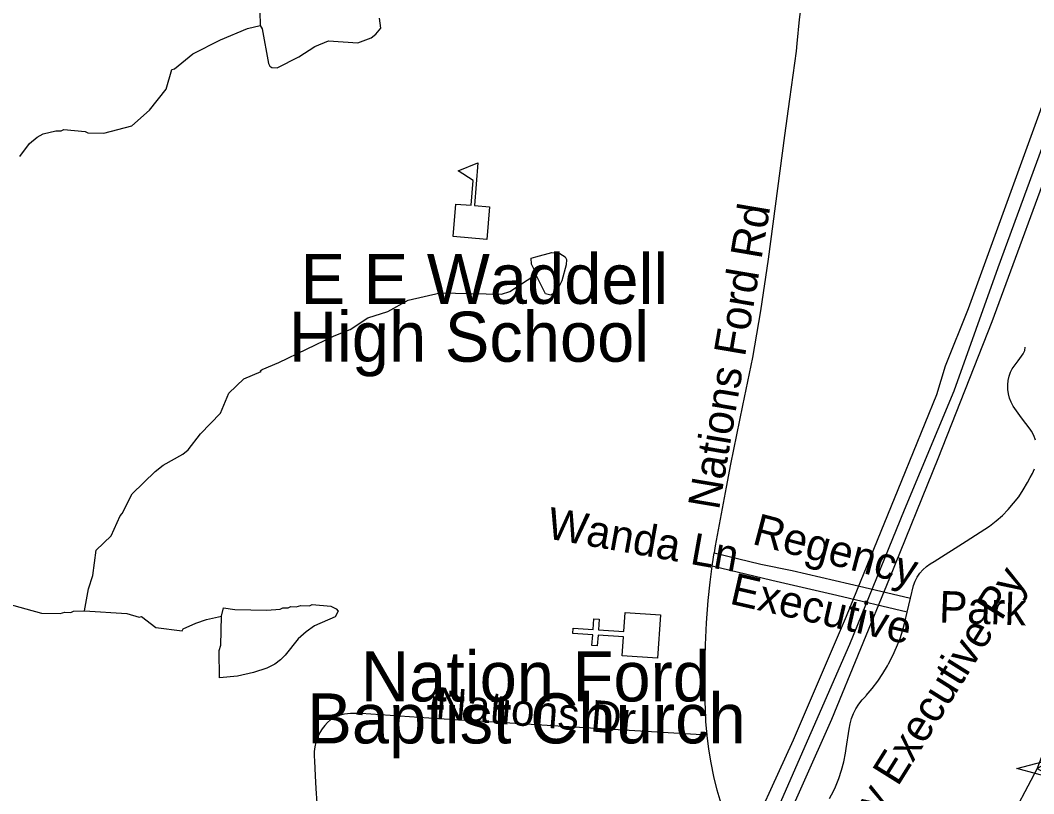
# Model space of a CAD drawing. Extents: x 1383679 to 1536984, y 460658 to 651027.
# Drawn here: x 1430703 to 1433744, y 515092 to 517411 of the extents above; entities that cross this region are included whole.
import ezdxf

# ---------------------------------------------------------------- set-up
doc = ezdxf.new("R2010")
doc.units = 0
for name, color, linetype in [('Exist Cultural Church CELL', 7, 'Continuous'), ('Exist Cultural Church Label', 7, 'Continuous'), ('Exist Cultural Educational Facility Elementary CELL', 7, 'Continuous'), ('Exist Cultural Educational Facility High Label', 7, 'Continuous'), ('Exist Hydrographic Misc Water Feature', 7, 'Continuous'), ('Exist Road Non-System Type 51', 7, 'Continuous'), ('Exist Road Non-System Type 51 Label', 7, 'Continuous'), ('Exist Road Primary Interstate Divided Center Attributed', 7, 'Continuous'), ('Exist Road Primary Interstate Structure Ovrhead Sign Attributed CELL', 7, 'Continuous'), ('Exist Utilities Electrical Transmission Line', 7, 'Continuous')]:
    doc.layers.add(name, color=color, linetype=linetype)

msp = doc.modelspace()

# ---------------------------------------------------------------- linework, layer by layer
at = {"layer": 'Exist Cultural Church CELL'}
msp.add_lwpolyline([(1432508.9, 515505.2), (1432512.6, 515562), (1432436.6, 515567.1), (1432434.5, 515535.1), (1432418.5, 515536.2), (1432420.7, 515568.1), (1432360.7, 515572.1), (1432361.7, 515588.1), (1432421.7, 515584.1), (1432423.9, 515616.1), (1432439.8, 515615), (1432437.7, 515583.1), (1432513.7, 515578), (1432517.6, 515635.5), (1432623.8, 515628.4), (1432615.1, 515498.1)], close=True, dxfattribs=at)
at = {"layer": 'Exist Cultural Educational Facility Elementary CELL'}
msp.add_lwpolyline([(1432001.9, 516762.6), (1432010, 516860.2), (1432055.9, 516856.4), (1432062.2, 516931.2), (1432017.3, 516959.3), (1432076.2, 516983.7), (1432065.5, 516855.6), (1432111.4, 516851.8), (1432103.2, 516754.2)], close=True, dxfattribs=at)
at = {"layer": 'Exist Hydrographic Misc Water Feature'}
for points in [[(1431421.6, 517438), (1431422.8, 517395.5)], [(1431422.8, 517395.5), (1431428.5, 517385.8), (1431448.2, 517281.4), (1431452, 517273.4), (1431457.9, 517269.2), (1431473.9, 517268.8), (1431538.6, 517301.4), (1431587.3, 517332.3), (1431627.7, 517349.3), (1431715.6, 517343.4), (1431756, 517358.5), (1431770.2, 517370.1), (1431784.6, 517387.8), (1431781.2, 517417.9)], [(1430702, 517002.3), (1430730.8, 517041.6), (1430753.3, 517061.1), (1430771.5, 517070.7), (1430809.7, 517079.8), (1430825.7, 517079.5), (1430833.8, 517083.3), (1430897.7, 517077.9), (1430905.6, 517073.7), (1430953.6, 517072.6), (1431038.1, 517094.7), (1431091.1, 517141.5), (1431140.5, 517204.4), (1431157.7, 517264), (1431165.8, 517265.8), (1431220.8, 517310.5), (1431303.7, 517352.6), (1431384.5, 517386.8), (1431422.8, 517395.5)], [(1432249.9, 516649.1), (1432248.8, 516655.7), (1432237.3, 516679.9), (1432235.9, 516697.5), (1432249.8, 516701.7), (1432298.1, 516714.5), (1432322, 516712), (1432337.8, 516701.7), (1432341.7, 516693.6), (1432341.3, 516677.6), (1432328.3, 516629.9), (1432311.6, 516598.3), (1432305.4, 516592.4), (1432295.4, 516586.7), (1432279.4, 516591), (1432249.9, 516649.1)], [(1430896.1, 515639.6), (1430908, 515706.2), (1430920.8, 515746), (1430930.4, 515821.7), (1430975.4, 515864.6), (1431003, 515925.4), (1431008.9, 515931.9), (1431038.2, 515991.2), (1431107.6, 516057.6), (1431132, 516077.1), (1431190.7, 516109.7), (1431207, 516123.4), (1431244.1, 516170.5), (1431303.4, 516233.1), (1431328.7, 516292.5), (1431373.7, 516335.5), (1431426.1, 516358.3), (1431422.3, 516360.4), (1431428.3, 516364.3), (1431478.7, 516385.1), (1431644.5, 516465.3), (1431693, 516484.3), (1431745.7, 516519.1), (1431806.2, 516537.7), (1431866.9, 516572.3), (1431963.4, 516594.1), (1432147.4, 516590), (1432171.5, 516597.5), (1432249.9, 516649.1)], [(1429860.1, 516317.6), (1429905.7, 516256.6), (1430028.4, 516105.8), (1430075.6, 516064.8), (1430122.9, 516037.8), (1430189.8, 515984.3), (1430276.9, 515940.4), (1430308.4, 515917.7), (1430347.6, 515880.8), (1430394.8, 515843.7), (1430457.6, 515784.4), (1430504.5, 515751.6), (1430552, 515710.2), (1430599.6, 515693.2), (1430601.4, 515687.2), (1430654.9, 515664), (1430766.3, 515633.5), (1430822.4, 515632.2), (1430836.4, 515635.9), (1430854.4, 515635.5), (1430862.5, 515639.3), (1430896.1, 515639.6)], [(1430896.1, 515639.6), (1431022.4, 515631.7), (1431060.1, 515621.5), (1431066.2, 515622.7), (1431109.4, 515589.8), (1431189.1, 515580), (1431191.4, 515585.9), (1431229.8, 515603.1), (1431262, 515614.3), (1431306.3, 515624.4)], [(1431306.3, 515624.4), (1431313, 515649.4), (1431346.7, 515644.4), (1431442.7, 515642.3), (1431482.7, 515645.3), (1431490.8, 515649.2), (1431506.8, 515648.8), (1431514.9, 515652.6), (1431530.9, 515652.3), (1431545, 515656), (1431571, 515655.4), (1431579.1, 515659.2), (1431635, 515654), (1431650.8, 515645.6), (1431656.6, 515639.5), (1431648.3, 515621.7), (1431585.7, 515595.1), (1431561.3, 515577.6), (1431536.9, 515556.2), (1431497.7, 515507.1), (1431483.5, 515493.4), (1431467.2, 515479.8), (1431442.9, 515468.3), (1431402.6, 515455.3), (1431354.4, 515444.3), (1431300.3, 515438.8), (1431300, 515521.5), (1431304.3, 515537.4), (1431306.3, 515624.4)]]:
    msp.add_lwpolyline(points, dxfattribs=at)
at = {"layer": 'Exist Road Non-System Type 51'}
msp.add_line((1433364.4, 515635.9), (1433374.2, 515678.2), dxfattribs=at)
for points in [[(1433055.7, 517525.4), (1433040.3, 517413.7), (1433033.3, 517341.9), (1433030.7, 517319.1), (1433011.1, 517174.8), (1432996.5, 517066), (1432946.7, 516694.7), (1432924.1, 516539.9), (1432900, 516400), (1432870.5, 516255.6), (1432834.4, 516080.2), (1432821, 516011.1), (1432788.2, 515835.4), (1432784.8, 515813.6)], [(1433748.9, 516152), (1433743.9, 516165.7), (1433737.5, 516178.8), (1433733.7, 516185.2), (1433707, 516219), (1433682.8, 516254.4), (1433676.5, 516266.1), (1433671.6, 516278.4), (1433668.2, 516291.2), (1433666.4, 516304.3), (1433666.1, 516317.5), (1433667.4, 516330.7), (1433670.3, 516343.6), (1433674.7, 516356.1), (1433679.4, 516366), (1433696.9, 516390.4), (1433712.8, 516410.5), (1433717, 516421.3), (1433718.7, 516431.1)], [(1433374.2, 515678.2), (1433382.8, 515715.9), (1433387.9, 515728.9), (1433394.5, 515741.3), (1433402.3, 515752.9), (1433411.5, 515763.5), (1433421.8, 515773), (1433433, 515781.3), (1433445.2, 515788.3), (1433541.5, 515849.3), (1433611.8, 515894.3), (1433631.4, 515909.6), (1433650, 515926.2), (1433667.5, 515943.9), (1433683.8, 515962.6), (1433699, 515982.4), (1433712.8, 516003), (1433725.3, 516024.6), (1433733.1, 516039.7), (1433740.3, 516052.4), (1433746.1, 516065.8)], [(1432778.8, 515773.9), (1432779.7, 515780.6), (1432784.8, 515813.6)], [(1432784.8, 515813.6), (1432924.8, 515780.2), (1433018.7, 515761.5), (1433234, 515711), (1433374.2, 515678.2)], [(1432764.1, 515267.1), (1432760.5, 515308.3), (1432758.9, 515338.7), (1432757.4, 515405.1), (1432757.5, 515471.5), (1432759.1, 515538), (1432762.4, 515604.3), (1432767.2, 515670.6), (1432772.7, 515725.7), (1432778.8, 515773.9)], [(1433364.4, 515635.9), (1433153.4, 515686), (1432957.9, 515731), (1432778.8, 515773.9)], [(1433130.9, 515077.6), (1433142.8, 515099.5), (1433149, 515112.4), (1433158.8, 515136.9), (1433167, 515161.9), (1433173.8, 515187.4), (1433179, 515213.2), (1433181.2, 515227.4), (1433190.2, 515285.5), (1433193, 515301.5), (1433197.3, 515317), (1433203.2, 515332.1), (1433210.4, 515346.5), (1433219.1, 515360.1), (1433229, 515372.9), (1433240.1, 515384.6), (1433241.4, 515385.8), (1433259.2, 515406.9), (1433275.8, 515428.9), (1433291.1, 515451.9), (1433305, 515475.6), (1433308.1, 515481.5), (1433321.1, 515506), (1433332.7, 515531.2), (1433342.8, 515557), (1433351.4, 515583.3), (1433357.6, 515606), (1433364.4, 515635.9)], [(1432764.1, 515267.1), (1432396.7, 515289.4), (1432075, 515309.3), (1431957.8, 515316.6), (1431725.9, 515331.7), (1431711.6, 515332.4), (1431693.4, 515332), (1431675.4, 515330), (1431663.4, 515327.6), (1431656.3, 515325.4), (1431648.7, 515322.5), (1431644.6, 515320), (1431634.1, 515313.2), (1431624.5, 515305.2), (1431616.5, 515295.9), (1431608.5, 515286.1), (1431602.1, 515274.9), (1431600.9, 515272.6), (1431594.7, 515259.7), (1431590, 515246.4), (1431586.7, 515232.6), (1431584.9, 515218.6), (1431584.6, 515204.5), (1431585.8, 515189.9), (1431588.2, 515145.3), (1431590.3, 515107.6), (1431598.9, 514975.7)], [(1432853.3, 514917.4), (1432837.1, 514968.6), (1432805.9, 515061.9), (1432794.5, 515102.2), (1432784.6, 515142.8), (1432776.2, 515183.8), (1432769.4, 515225.1), (1432764.2, 515266.6), (1432764.1, 515267.1)]]:
    msp.add_lwpolyline(points, dxfattribs=at)
at = {"layer": 'Exist Road Primary Interstate Divided Center Attributed'}
msp.add_lwpolyline([(1434792.2, 518497.9), (1434771.6, 518430.6), (1434687.2, 518142.5), (1434645.4, 517998.2), (1434587, 517820.2), (1434521.5, 517611.2), (1434427.2, 517293.6), (1434330.2, 516967.1), (1434222.5, 516626.2), (1434131.1, 516331.3), (1434065.6, 516116.8), (1434007.1, 515926.4), (1433922.1, 515639.8), (1433859.8, 515448), (1433839.9, 515390.2), (1433803.8, 515299.5), (1433754.3, 515167.2), (1433661.4, 514990.9)], dxfattribs=at)
at = {"layer": 'Exist Road Primary Interstate Structure Ovrhead Sign Attributed CELL'}
msp.add_lwpolyline([(1433811.1, 515135.6), (1433693.4, 515167.2), (1433811.1, 515198.7), (1433754.3, 515167.2)], close=True, dxfattribs=at)
at = {"layer": 'Exist Utilities Electrical Transmission Line'}
for points in [[(1432134, 512767.1), (1432381.7, 513046.2), (1432422.5, 513091.6), (1432431.9, 513165.3), (1432418.2, 513377.9), (1432408.5, 513600), (1432405.7, 513658), (1432437.3, 513747.6), (1432583.5, 514060.8), (1432819.7, 514574.5), (1432968.6, 514933.7), (1433138.2, 515314.7), (1433312.6, 515739.3), (1433457.7, 516096.8), (1433619.8, 516507.7), (1433826.9, 517070), (1434059.4, 517705.6)], [(1432252.2, 512974.8), (1432362.3, 513082.7), (1432380.1, 513176.3), (1432370.1, 513382.6), (1432358.6, 513605), (1432359.5, 513661), (1432397.3, 513750.3), (1432572.8, 514129.1), (1432796.7, 514625), (1432960.2, 515009.9), (1433192.7, 515539.7), (1433356.5, 515942.6), (1433505.6, 516299.9), (1433636.9, 516669.4), (1433782.7, 517064.7), (1433970.9, 517585.3)], [(1431839.7, 512552.7), (1432259.4, 513044.7), (1432307, 513119.8), (1432336.8, 513209.2), (1432325, 513529.6), (1432320.3, 513591.7), (1432309.8, 513676), (1432363.9, 513780.9), (1432550.2, 514195.6), (1432744.6, 514622.1), (1432866.3, 514909.7), (1433022.9, 515252.8), (1433182.2, 515623.9), (1433348.3, 516030.8), (1433453.4, 516289), (1433479.1, 516374.5), (1433548.4, 516547.2), (1433760, 517129.4), (1433910.1, 517546.5)]]:
    msp.add_lwpolyline(points, dxfattribs=at)

# ---------------------------------------------------------------- texts
at = {"layer": 'Exist Cultural Church Label'}
for s, p in [('Nation Ford', (1431724.7, 515368.4)), ('Baptist Church', (1431564.2, 515242.5))]:
    msp.add_text(s, height=150, rotation=0, dxfattribs=at).set_placement(p)
at = {"layer": 'Exist Cultural Educational Facility High Label'}
for s, p in [('E E Waddell', (1431543.7, 516560.8)), ('High School', (1431508.4, 516387.3))]:
    msp.add_text(s, height=150, rotation=0, dxfattribs=at).set_placement(p)
at = {"layer": 'Exist Road Non-System Type 51 Label'}
for s, rotation, p in [('Nations Ford Rd', 80.3897, (1432799.5, 515940.2)), ('Wanda Ln', 349.8761, (1432278.9, 515858.2)), ('Regency', 345.2572, (1432895.9, 515841.4)), ('Regency Executive Py', 58.0009, (1433051.7, 514655.6)), ('Executive', 347.1258, (1432828.3, 515662.1)), ('Park Dr', 357.9913, (1433458.9, 515605.2)), ('Nations Dr', 355.2764, (1431947.4, 515317))]:
    msp.add_text(s, height=95, rotation=rotation, dxfattribs=at).set_placement(p)

doc.saveas('drawing.dxf')
